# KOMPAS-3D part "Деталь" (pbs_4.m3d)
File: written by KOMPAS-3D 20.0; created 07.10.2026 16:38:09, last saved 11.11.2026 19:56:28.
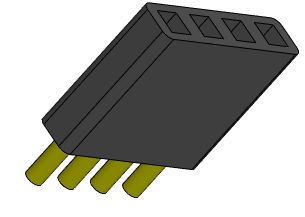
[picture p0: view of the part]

Document properties: Полное имя файла: D:\myProjects\Progect_esp32\box_compas\разъемы\pbs_4.m3d

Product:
- Part/product: Деталь
    Масса: 0.00125697

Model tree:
1. Эскиз:1
2. Элемент выдавливания:1
     Расстояние 1 = 8.5
3. Эскиз:2  (with: Элемент выдавливания:1)
4. Элемент выдавливания:2
     Расстояние 1 = 3
5. Массив по сетке:2  (with: Элемент выдавливания:2, Эскиз:2)  (4 pattern instances)
     Шаг 1 = 2.54; Угол раствора = 90
6. Эскиз:3  (with: Элемент выдавливания:1)
7. Элемент выдавливания:3
     Расстояние 2 = 8
8. Массив по сетке:3  (with: Элемент выдавливания:3, Эскиз:3)  (4 pattern instances)
     Шаг 1 = 2.54; Угол раствора = 90; Геометрический массив = 128
9. Скругление:1  (with: Элемент выдавливания:1)
     Радиус = 0.5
